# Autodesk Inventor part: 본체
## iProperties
Created: 2015-05
Part Number: 본체
Document SubType Name: Modeling
Designer: elite
Density: 1.06 g/cm^3
Material: ABS 플라스틱
Mass: 132.817 g
Surface Area: 327.579 cm^2
Volume: 125.299 cm^3
Author: elite
